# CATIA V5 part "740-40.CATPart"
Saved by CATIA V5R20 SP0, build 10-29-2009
Part number: 740-40
Bounding box of the stored display mesh (mm): x -32.9 to 32.9, y -31 to 32.9, z -37 to 15
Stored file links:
  C:\Users\Utente\Desktop\IO LAVORO\3D X SITO CF\X SITO\740\740-40.CATPart
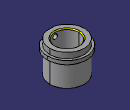
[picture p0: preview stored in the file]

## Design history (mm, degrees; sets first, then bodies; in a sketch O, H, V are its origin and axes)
Set1
  DatumSurface1 to DatumSurface35 "740-40"
Body1 (main body)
